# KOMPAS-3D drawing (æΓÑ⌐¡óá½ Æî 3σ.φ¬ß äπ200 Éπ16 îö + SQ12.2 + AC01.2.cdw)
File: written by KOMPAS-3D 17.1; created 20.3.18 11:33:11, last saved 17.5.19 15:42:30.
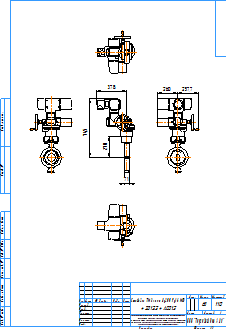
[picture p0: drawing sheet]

Sheet 1: A3, portrait

Title block, sheet 1: name: Стейнвал ТМ 3х.экс Ду200 Ру16 МФ / + SQ12.2 + AC01.2; mass: 63; sheets: 1; organisation: ООО "Торговый дом АДЛ"; sheet format: A3; stored path: \\adlc.lan\data\АДЛ_ПКД\3D-модели\ADL production\Дисковые поворотные затворы СТЕЙНВАЛ\Трехэксцентриковый\Стейнвал м-ф\С эл.приводом\KOMPAS 2D\Стейнвал ТМ 3х.экс Ду200 Ру16 МФ + SQ12.2.cdw

Views: Спереди 6, Проекционный вид 8, Проекционный вид 9, Проекционный вид 10
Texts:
  kka
  adl
  Рама для чертежей
  Лит-Масса-Масштаб
  Материал-Предприятие
  Масштаб
  Изм.
  Лист
  № докум.
  Подп.
  Дата
  Лит.
  Разраб.
  Пров.
  Т.контр.
  Листов
  Внимание! Данный продукт является объектом авторского права ООО «Торговый Дом АДЛ».
  Запрещается изменение, копирование, распространение
  (в том числе путем копирования на другие сайты и ресурсы в Интернете)
  или любое иное использование информации и объектов без предварительного
  согласия правообладателя (ООО «Торговый Дом АДЛ»).
  Н.контр.
  Утв.
  Изменение
  Номер документа
  Подпись
  Обозначение документа
  Наименование изделия
  Масса изделия по ГОСТ 2.109-73
  Порядковый номер листа
  Общее количество листов в документе
  Характер работы, выполненной лицом, подписавшим документ
  Наименование или индекс предприятия, выпускающего документ
  Инв. № подл.
  Подп. и дата
  Взам. инв. №
  Инв. № дубл.
  Инвентарный номер подлинника по ГОСТ 2.501-68
  Подпись принявшего подлинник в отдел технической документации
  Инвентарный номер подлинника, взамен которого выпущен данный подлинник
  Инвентарный номер дубликата по ГОСТ 2.502-68
  Подпись принявшего дубликат в отдел технической документации
  Справ. №
  Перв. примен.
  Обозначение документа, взамен или на основании которого выпущен данный документ
  Обозначение документа, в котором впервые записан данный документ
  Подпись лица, копировавшего чертеж
  Обозначение формата листа
  !Рама для чертежа
Dimensions and other numbers on the sheet: 71; 270; 745; 378; 257,7; 260; 1:10; 1; 63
